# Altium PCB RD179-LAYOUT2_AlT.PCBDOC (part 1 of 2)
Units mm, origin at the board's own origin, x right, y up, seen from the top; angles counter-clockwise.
Board outline 130 x 85 mm, 2 copper layers (TOP, BOTTOM), stack 0 mm thick; 157 components, 104 nets, 823 pads, 0 vias.
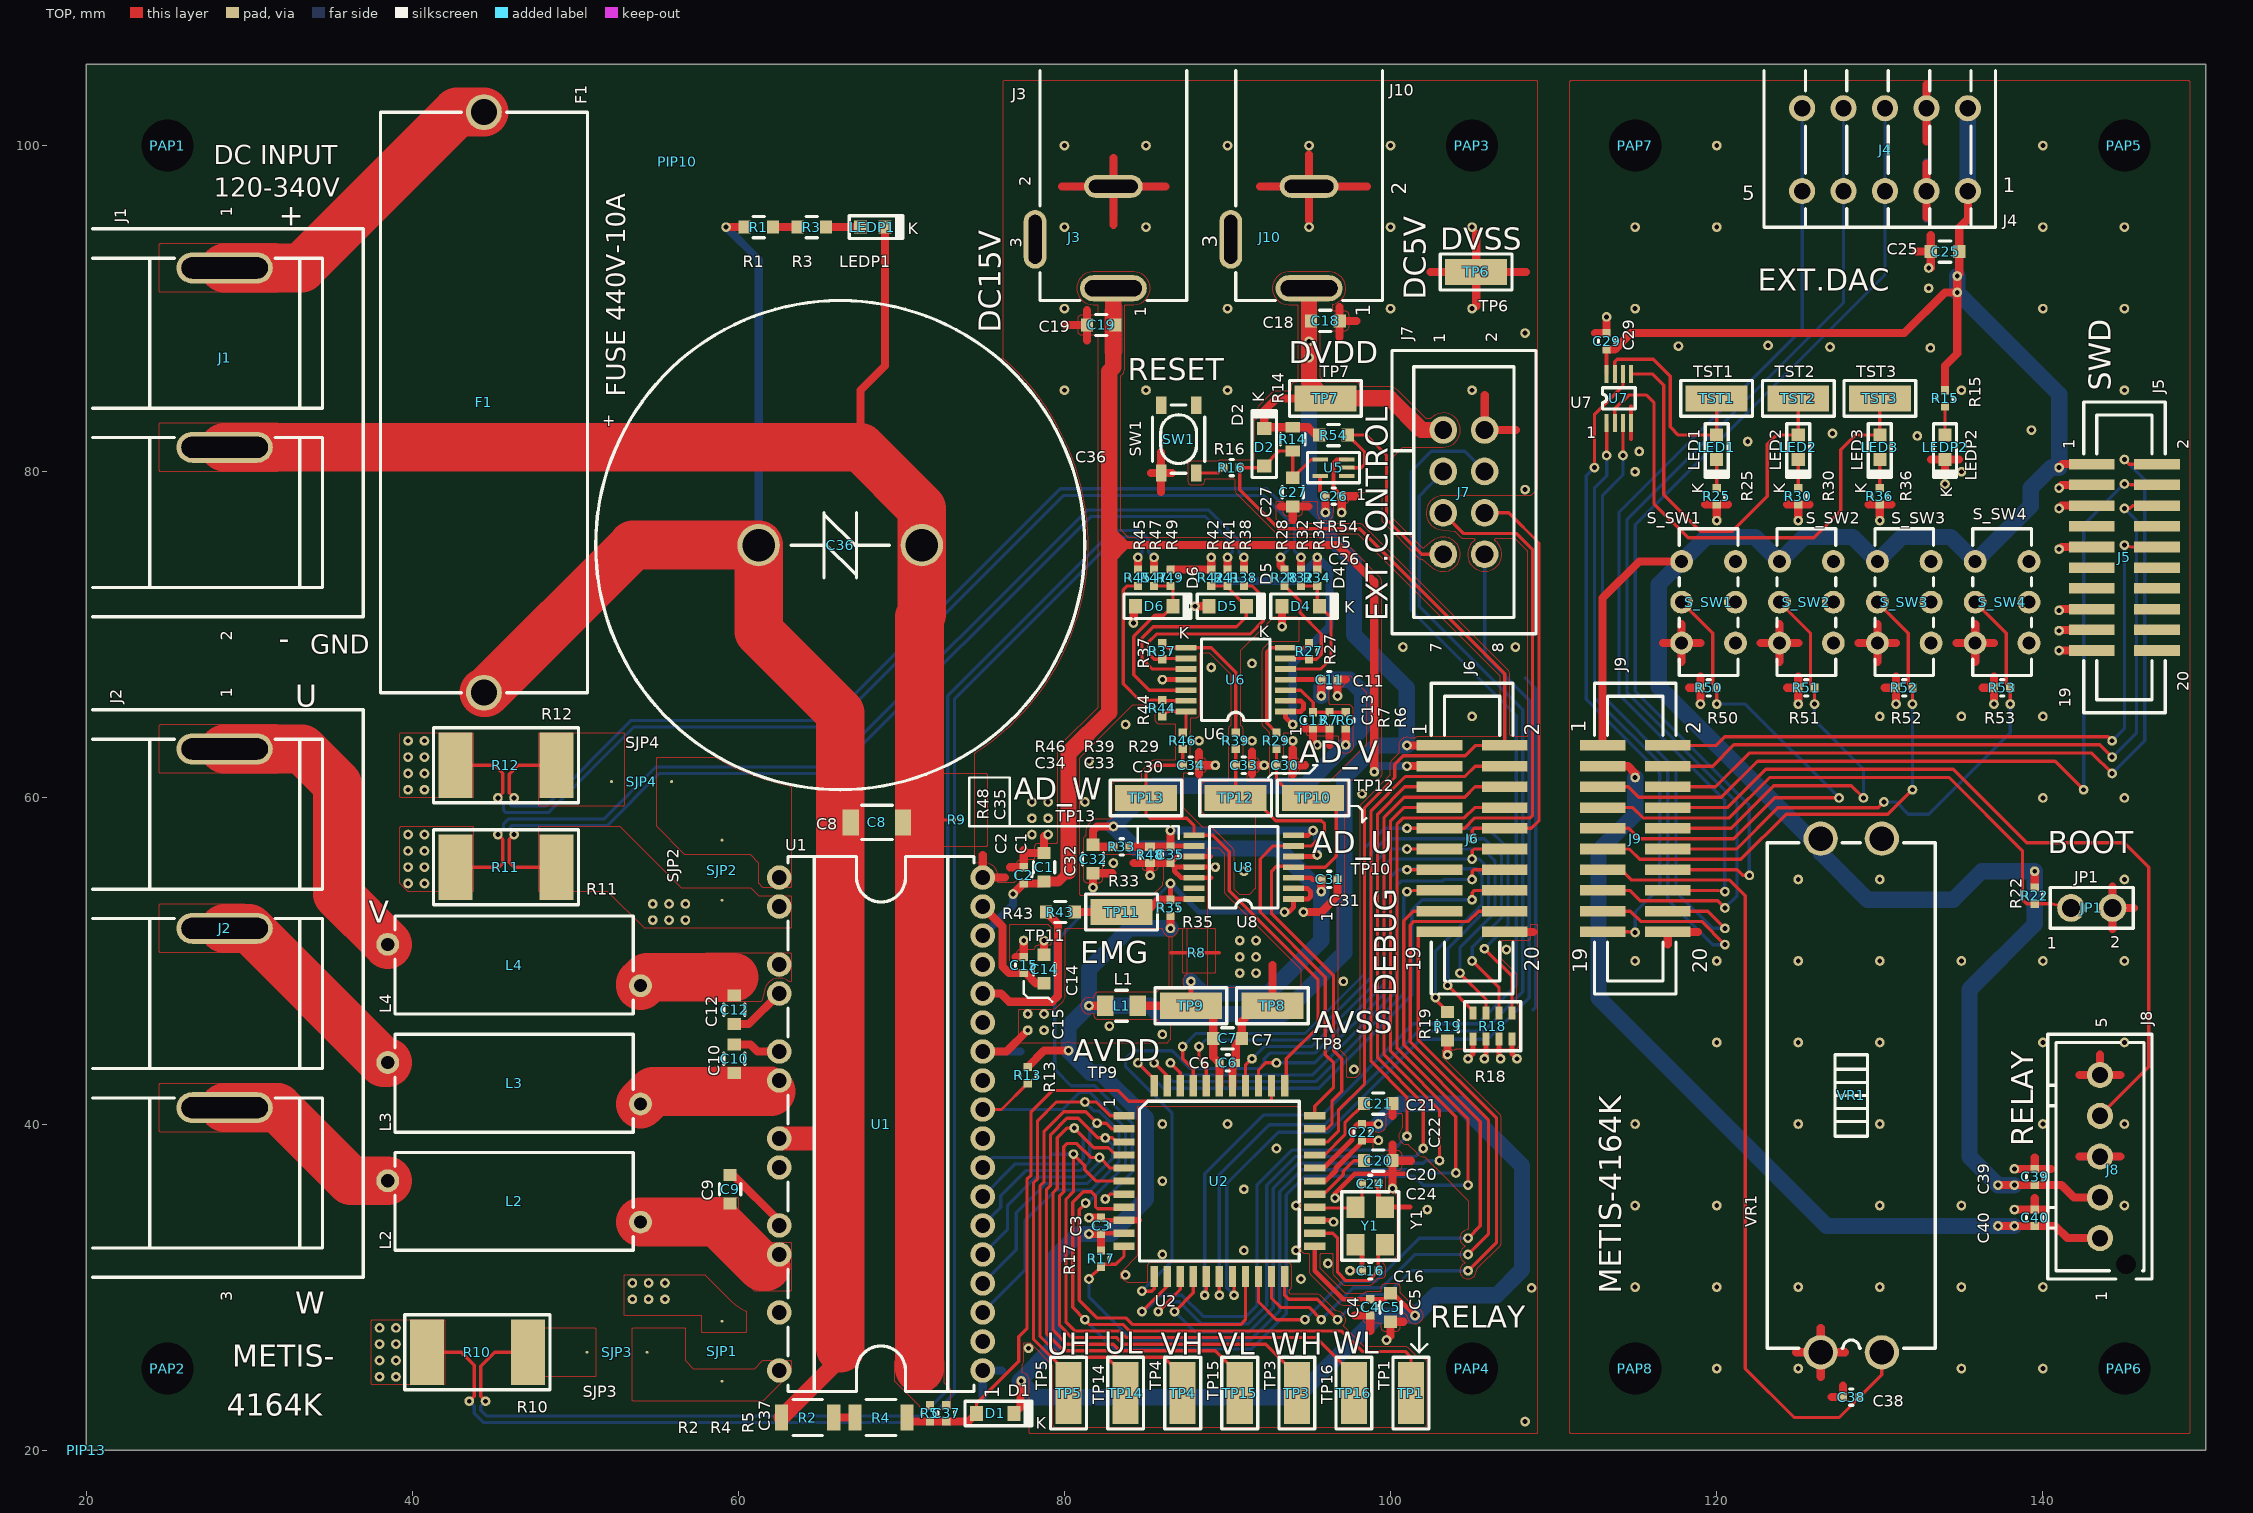
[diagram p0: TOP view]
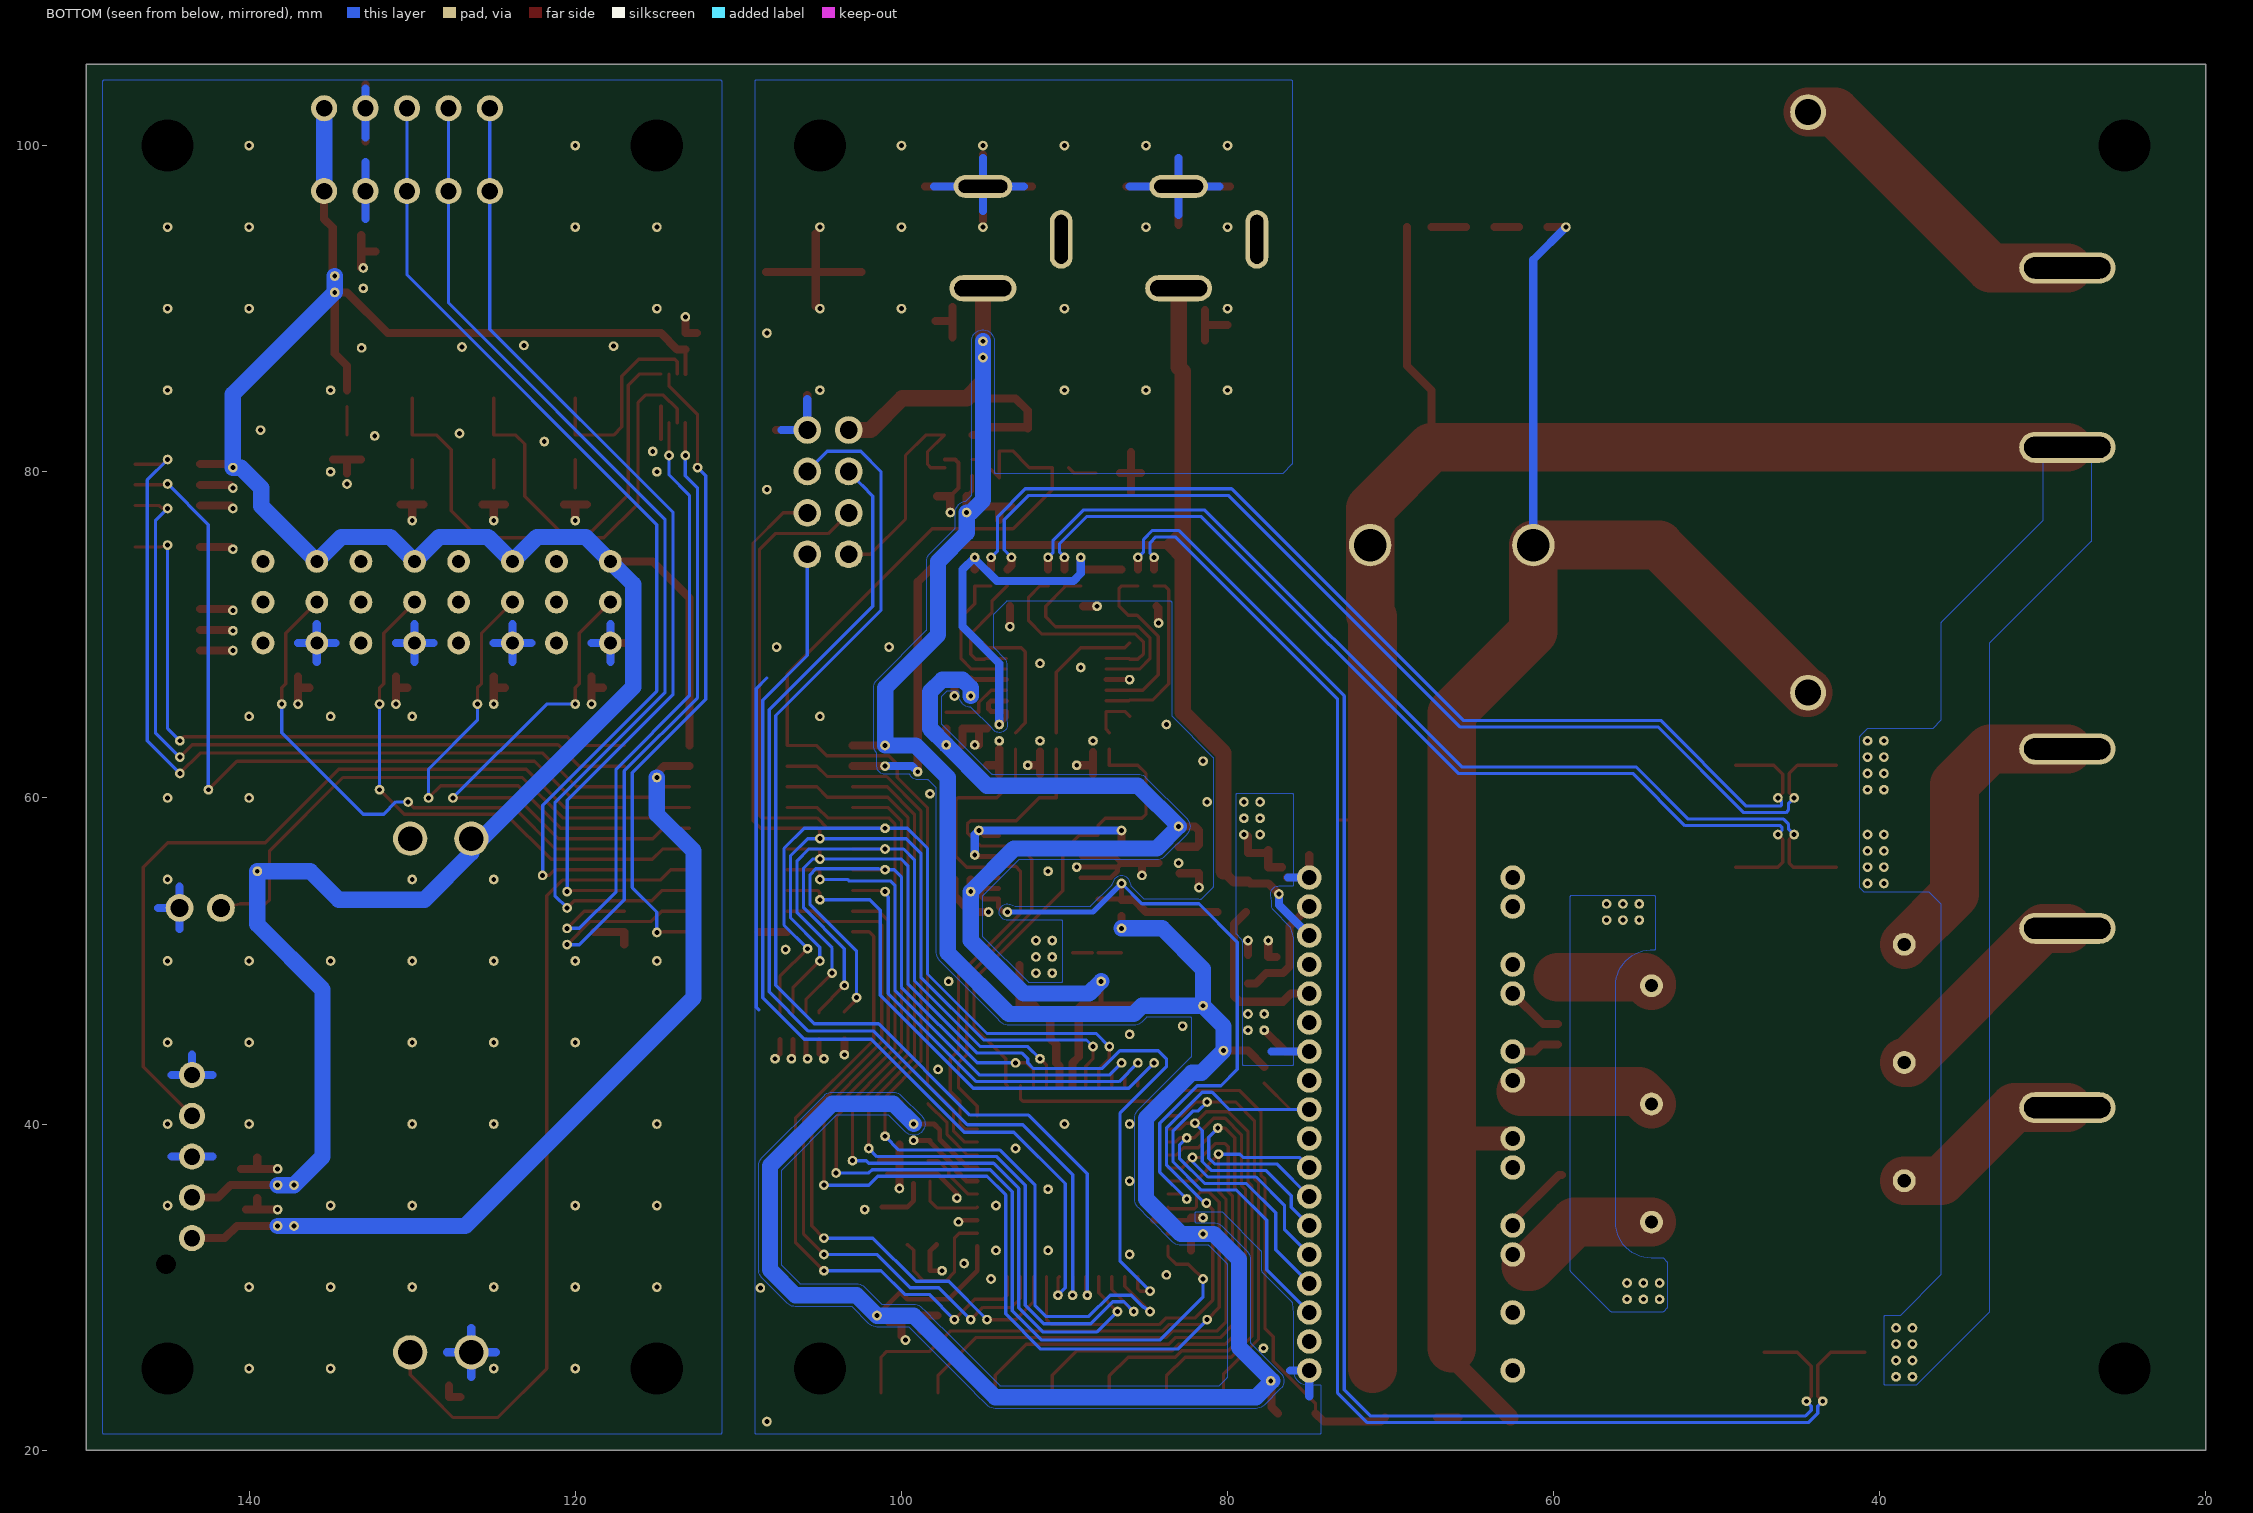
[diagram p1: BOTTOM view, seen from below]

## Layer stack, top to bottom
Top Solder: solder mask 0.0102, Solder Resist, Dk 3.5
TOP: signal copper (thickness not stored)
BOTTOM: signal copper (thickness not stored)
Bottom Solder: solder mask 0.0102, Solder Resist, Dk 3.5

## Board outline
20,20 20,105 150,105 150,20

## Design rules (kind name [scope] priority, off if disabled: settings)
AssemblyTestPointUsage [All] p0: scope1count=1 scope1_0_kind=Board scope1_0_value=Board scope2count=1 scope2_0_kind=Board scope2_0_value=Board commentlength=0
AssemblyTestpoint [All] p0: scope1count=1 scope1_0_kind=Board scope1_0_value=Board scope2count=1 scope2_0_kind=Board scope2_0_value=Board commentlength=0
Clearance [All] p0: scope1count=1 scope1_0_kind=Board scope1_0_value=Board scope2count=1 scope2_0_kind=Board scope2_0_value=Board commentlength=0 gap=0.2
Clearance [All] p1: gap=0.2 ignorepadtopadclearanceinfootprint=TRUE except(0.3: SMDPad-THPad THPad-THPad THPad-Via Via-Via; 0.5: SMDPad-SMDPad; 1: Arc-Hole Track-Hole SMDPad-Hole THPad-Hole Via-Hole Fill-Hole Poly-Hole Region-Hole Text-Hole)
ComponentClearance [All] p0: scope1count=1 scope1_0_kind=Board scope1_0_value=Board scope2count=1 scope2_0_kind=Board scope2_0_value=Board commentlength=0 gap=0.254 collisioncheckmode=3
DiffPairsRouting [All] p0: scope1count=1 scope1_0_kind=Board scope1_0_value=Board scope2count=1 scope2_0_kind=Board scope2_0_value=Board commentlength=0
FabricationTestPointUsage [All] p0: scope1count=1 scope1_0_kind=Board scope1_0_value=Board scope2count=1 scope2_0_kind=Board scope2_0_value=Board commentlength=0 valid=0 allowmultiple=FALSE
FabricationTestpoint [All] p0: scope1count=1 scope1_0_kind=Board scope1_0_value=Board scope2count=1 scope2_0_kind=Board scope2_0_value=Board commentlength=0 side=3 testpointundercomponent=TRUE minsize=1.016 maxsize=2.54 preferedsize=1.524 minholesize=0 maxholesize=1.016 preferedholesize=0.813 testpointgrid=0.025
FanoutControl Fanout_BGA [All] p0 off: scope1count=1 scope1_0_kind=Board scope1_0_value=Board scope2count=1 scope2_0_kind=Board scope2_0_value=Board commentlength=69 // Protel DXP Scope 1 Expression Was: IsBGA   Fanout_BGA (Default Rule)
FanoutControl Fanout_LCC [All] p0 off: scope1count=1 scope1_0_kind=Board scope1_0_value=Board scope2count=1 scope2_0_kind=Board scope2_0_value=Board commentlength=69 // Protel DXP Scope 1 Expression Was: IsLCC   Fanout_LCC (Default Rule)
FanoutControl Fanout_SOIC [All] p0 off: scope1count=1 scope1_0_kind=Board scope1_0_value=Board scope2count=1 scope2_0_kind=Board scope2_0_value=Board commentlength=71 // Protel DXP Scope 1 Expression Was: IsSOIC   Fanout_SOIC (Default Rule)
FanoutControl Fanout_Small [All] p0 off: scope1count=1 scope1_0_kind=Board scope1_0_value=Board scope2count=1 scope2_0_kind=Board scope2_0_value=Board commentlength=84 // Protel DXP Scope 1 Expression Was: (CompPinCount < 5)   Fanout_Small (Default Rule)
FanoutControl Fanout_Default [All] p0: scope1count=1 scope1_0_kind=Board scope1_0_value=Board scope2count=1 scope2_0_kind=Board scope2_0_value=Board commentlength=30 // Fanout_Default (Default Rule)
Height [All] p0: scope1count=1 scope1_0_kind=Board scope1_0_value=Board scope2count=1 scope2_0_kind=Board scope2_0_value=Board commentlength=0
HoleSize [All] p0: scope1count=1 scope1_0_kind=Board scope1_0_value=Board scope2count=1 scope2_0_kind=Board scope2_0_value=Board commentlength=0 absolutevalues=TRUE maxlimit=100 minlimit=0.001 maxpercent=80.000 minpercent=20.000
HoleSize [All] p1: absolutevalues=TRUE maxlimit=100 minlimit=0.001 maxpercent=80.000 minpercent=20.000
HoleToHoleClearance [All] p0: scope1count=1 scope1_0_kind=Board scope1_0_value=Board scope2count=1 scope2_0_kind=Board scope2_0_value=Board commentlength=0
HoleToHoleClearance [All] p1: gap=0.6 allowstackedmicrovias=FALSE
LayerPairs [All] p0: scope1count=1 scope1_0_kind=Board scope1_0_value=Board scope2count=1 scope2_0_kind=Board scope2_0_value=Board commentlength=0 enforce=TRUE
MinimumSolderMaskSliver [All] p0: scope1count=1 scope1_0_kind=Board scope1_0_value=Board scope2count=1 scope2_0_kind=Board scope2_0_value=Board commentlength=0
MinimumSolderMaskSliver [All] p1: minsoldermaskwidth=0.15
NetAntennae [All] p0: scope1count=1 scope1_0_kind=Board scope1_0_value=Board scope2count=1 scope2_0_kind=Board scope2_0_value=Board commentlength=0
NetAntennae [All] p1: netantennaetolerance=100
PasteMaskExpansion [All] p0: scope1count=1 scope1_0_kind=Board scope1_0_value=Board scope2count=1 scope2_0_kind=Board scope2_0_value=Board commentlength=0 expansion=0
PlaneClearance [All] p0: scope1count=1 scope1_0_kind=Board scope1_0_value=Board scope2count=1 scope2_0_kind=Board scope2_0_value=Board commentlength=0 clearance=0.001
PlaneClearance [All] p1: clearance=0.001
PlaneConnect [All] p0: scope1count=1 scope1_0_kind=Board scope1_0_value=Board scope2count=1 scope2_0_kind=Board scope2_0_value=Board commentlength=0 planeconnectstyle=Direct reliefexpansion=0.508 reliefentries=4 reliefconductorwidth=0.254 reliefairgap=0.254
PlaneConnect [All] p1: planeconnectstyle=Direct reliefexpansion=0.508 reliefentries=4 reliefconductorwidth=0.254 reliefairgap=0.254
PolygonConnect [All] p0: scope1count=1 scope1_0_kind=Board scope1_0_value=Board scope2count=1 scope2_0_kind=Board scope2_0_value=Board commentlength=0 connectstyle=Direct reliefconductorwidth=0.254 reliefentries=4 polygonreliefangle="90 Angle"
PolygonConnect [All] p1: connectstyle=Direct reliefconductorwidth=0.254 reliefentries=4 polygonreliefangle="90 Angle" airgapwidth=0.254
RoutingCorners [All] p0: scope1count=1 scope1_0_kind=Board scope1_0_value=Board scope2count=1 scope2_0_kind=Board scope2_0_value=Board commentlength=0 cornerstyle=45-Degree minsetback=2.54 maxsetback=2.54
RoutingLayers [All] p0: scope1count=1 scope1_0_kind=Board scope1_0_value=Board scope2count=1 scope2_0_kind=Board scope2_0_value=Board commentlength=0 top layer=Automatic bottom layer=Automatic
RoutingPriority [All] p0: scope1count=1 scope1_0_kind=Board scope1_0_value=Board scope2count=1 scope2_0_kind=Board scope2_0_value=Board commentlength=0
RoutingTopology [All] p0: scope1count=1 scope1_0_kind=Board scope1_0_value=Board scope2count=1 scope2_0_kind=Board scope2_0_value=Board commentlength=0 topology=Shortest
RoutingVias [All] p0: scope1count=1 scope1_0_kind=Board scope1_0_value=Board scope2count=1 scope2_0_kind=Board scope2_0_value=Board commentlength=0 holewidth=0.1 width=0.1 viastyle="Through Hole" minholewidth=0.001 minwidth=0.001 maxholewidth=100 maxwidth=100
RoutingVias [All] p1: holewidth=0.1 width=0.1 viastyle="Through Hole" minholewidth=0.001 minwidth=0.001 maxholewidth=100 maxwidth=100
ShortCircuit [All] p0: scope1count=1 scope1_0_kind=Board scope1_0_value=Board scope2count=1 scope2_0_kind=Board scope2_0_value=Board commentlength=0 allowed=FALSE
SilkToBoardRegionClearance [All] p0: scope1count=1 scope1_0_kind=Board scope1_0_value=Board scope2count=1 scope2_0_kind=Board scope2_0_value=Board commentlength=0
SilkToSilkClearance [All] p0: scope1count=1 scope1_0_kind=Board scope1_0_value=Board scope2count=1 scope2_0_kind=Board scope2_0_value=Board commentlength=0
SilkToSilkClearance [All] p1: silktosilkclearance=0.001
SilkToSolderMaskClearance [All] p0 off: scope1count=1 scope1_0_kind=Board scope1_0_value=Board scope2count=1 scope2_0_kind=Board scope2_0_value=Board commentlength=44 // Protel DXP Scope 1 Expression Was: IsPad
SilkToSolderMaskClearance [IsPad] p1: minsilkscreentomaskgap=0.15 clearancetoexposedcopper=TRUE
SolderMaskExpansion [All] p0: scope1count=1 scope1_0_kind=Board scope1_0_value=Board scope2count=1 scope2_0_kind=Board scope2_0_value=Board commentlength=0 expansion=0.001
SolderMaskExpansion [All] p1: expansion=0.001
UnRoutedNet [All] p0: scope1count=1 scope1_0_kind=Board scope1_0_value=Board scope2count=1 scope2_0_kind=Board scope2_0_value=Board commentlength=0
UnpouredPolygon [All] p0: scope1count=1 scope1_0_kind=Board scope1_0_value=Board scope2count=1 scope2_0_kind=Board scope2_0_value=Board commentlength=0
Width [All] p0: scope1count=1 scope1_0_kind=Board scope1_0_value=Board scope2count=1 scope2_0_kind=Board scope2_0_value=Board commentlength=0 maxlimit=1000 minlimit=2539.975 preferedwidth=0
Width [All] p1: maxlimit=1000 minlimit=2539.975 preferedwidth=0 toplayer_minwidth=0 bottomlayer_minwidth=0 minimp=50.000000 maximp=50.000000 favimp=50.000000
22 further rules are at their usual default settings.

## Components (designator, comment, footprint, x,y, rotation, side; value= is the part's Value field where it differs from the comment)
C1 "CRC1608DEF-R" CRC1608DEF-R 78.75,55.75 r90 top
C2 "CRC1005DEF-R" CRC1005DEF-R 77.5,55.25 r90 top
C3 "CRC1005DEF-R" CRC1005DEF-R 82.25,33.75 r90 top
C4 "CRC1005DEF-R" CRC1005DEF-R 98.75,28.75 r270 top
C5 "CRC1608DEF-R" CRC1608DEF-R 100,28.75 r270 top
C6 "CRC1005DEF-R" CRC1005DEF-R 90,43.75 r0 top
C7 "CRC1608DEF-R" CRC1608DEF-R 90,45.25 r0 top
C8 "CC3216DEF-R" CC3216DEF-R 68.5,58.5 r0 top
C9 "CRC1608DEF-R" CRC1608DEF-R 59.5,36 r270 top
C10 "CRC1608DEF-R" CRC1608DEF-R 59.75,44 r270 top
C11 "CRC1005DEF-R" CRC1005DEF-R 96.25,67.25 r180 top
C12 "CRC1608DEF-R" CRC1608DEF-R 59.75,47 r90 top
C13 "CRC1005DEF-R" CRC1005DEF-R 95.25,64.75 r90 top
C14 "CRC1608DEF-R" CRC1608DEF-R 78.75,49.5 r90 top
C15 "CRC1005DEF-R" CRC1005DEF-R 77.5,49.75 r90 top
C16 "CRC1005DEF-R" CRC1005DEF-R 98.75,31 r180 top
C18 "CRC1608DEF-R" CRC1608DEF-R 96,89.25 r0 top
C19 "CRC1608DEF-R" CRC1608DEF-R 82.25,89 r180 top
C20 "CRC1608DEF-R" CRC1608DEF-R 99.25,37.75 r0 top
C21 "CRC1608DEF-R" CRC1608DEF-R 99.25,41.25 r0 top
C22 "CRC1005DEF-R" CRC1005DEF-R 98.25,39.5 r270 top
C24 "CRC1005DEF-R" CRC1005DEF-R 98.75,36.35 r0 top
C25 "CRC1608DEF-R" CRC1608DEF-R 134,93.5 r180 top
C26 "CRC1005DEF-R" CRC1005DEF-R 96.5,78.5 r0 top
C27 "CRC1608DEF-R" CRC1608DEF-R 94,78.75 r270 top
C29 "CRC1005DEF-R" CRC1005DEF-R 113.25,88 r90 top
C30 "CRC1005DEF-R" CRC1005DEF-R 93.5,62 r0 top
C31 "CRC1005DEF-R" CRC1005DEF-R 96.25,55 r0 top
C32 "CRC1608DEF-R" CRC1608DEF-R 81.75,56.25 r270 top
C33 "CRC1005DEF-R" CRC1005DEF-R 91,62 r0 top
C34 "CRC1005DEF-R" CRC1005DEF-R 87.75,62 r0 top
C35 "CRC1005DEF-R" CRC1005DEF-R 86.5,56.5 r270 top
C36 "DDC300000" DDC300000 66.25,75.5 r0 top
C37 "CRC1005DEF-R" CRC1005DEF-R 72.75,22.25 r90 top
C38 "CRC1005DEF-R" CRC1005DEF-R 128.25,23.25 r180 top
C39 "CRC1005DEF-R" CRC1005DEF-R 139.5,36.75 r90 top
C40 "CRC1005DEF-R" CRC1005DEF-R 139.5,34.25 r90 top
D1 "CDUSC05-R" CDUSC05-R 75.75,22.25 r180 top
D2 "CDUSC05-R" CDUSC05-R 92.25,81.5 r270 top
D4 "CDUSC05-R" CDUSC05-R 94.5,71.75 r180 top
D5 "CDUSC05-R" CDUSC05-R 90,71.75 r180 top
D6 "CDUSC05-R" CDUSC05-R 85.5,71.75 r180 top
F1 "DFU351200" DFU351200 44.4,84.25 r270 top
J1 "OTB-650-2P_R00" OTB-650-2P_R00 28.5,83 r270 top
J2 "OTB-650-3P_R00" OTB-650-3P_R00 28.5,48 r270 top
J3 "2DC-0005D100_R00" 2DC-0005D100_R00 83,91.25 r90 top
J4 "ML-700-NV-5P_R00" ML-700-NV-5P_R00 130,100 r180 top
J5 "3220-20-0300-00_R00-R" 3220-20-0300-00_R00-R 145,74.75 r270 top
J6 "3220-20-0300-00_R00-R" 3220-20-0300-00_R00-R 105,57.5 r270 top
J7 "75869-332LF_R00" 75869-332LF_R00 104.5,78.75 r270 top
J8 "B05B-XASK-1-A_R00" B05B-XASK-1-A_R00 143.5,38 r270 top
J9 "3220-20-0300-00_R00-R" 3220-20-0300-00_R00-R 115,57.5 r270 top
J10 "2DC-0005D100_R00" 2DC-0005D100_R00 95,91.25 r90 top
JP1 "PH-1X02SG_R00" PH-1X02SG_R00 143,53.25 r0 top
L1 "CL2125DEF-R" CL2125DEF-R 83.5,47.25 r180 top
L2 "DL146001" DL146001 46.25,35.25 r0 top
L3 "DL146001" DL146001 46.25,42.5 r0 top
L4 "DL146001" DL146001 46.25,49.75 r0 top
LED1 "LTST-C190_R00-R" LTST-C190_R00-R 120,81.5 r90 top
LED2 "LTST-C190_R00-R" LTST-C190_R00-R 125,81.5 r90 top
LED3 "LTST-C190_R00-R" LTST-C190_R00-R 130,81.5 r90 top
LEDP1 "LTST-C190_R00-R" LTST-C190_R00-R 68.25,95 r180 top
LEDP2 "LTST-C190_R00-R" LTST-C190_R00-R 134,81.5 r90 top
PAP1 "NH3.2-00" NH3.2-00 25,100 r0 top
PAP2 "NH3.2-00" NH3.2-00 25,25 r0 top
PAP3 "NH3.2-00" NH3.2-00 105,100 r0 top
PAP4 "NH3.2-00" NH3.2-00 105,25 r0 top
PAP5 "NH3.2-00" NH3.2-00 145,100 r0 top
PAP6 "NH3.2-00" NH3.2-00 145,25 r0 top
PAP7 "NH3.2-00" NH3.2-00 115,100 r0 top
PAP8 "NH3.2-00" NH3.2-00 115,25 r0 top
PIP10 "LOGO-TOSHIBA_NEW" LOGO-TOSHIBA_NEW 56.25,99 r0 top
PIP11 "L2-00" L2-00 20,1.5 r0 top
PIP12 "ANAKOUSA-00" ANAKOUSA-00 163,-20 r0 top
PIP13 "ZAHYO_ORG-00" ZAHYO_ORG-00 20,20 r0 top
R1 "CRC1608DEF-R" CRC1608DEF-R 61.25,95 r0 top
R2 "CR3216DEF-R" CR3216DEF-R 64.25,22 r0 top
R3 "CRC1608DEF-R" CRC1608DEF-R 64.5,95 r0 top
R4 "CR3216DEF-R" CR3216DEF-R 68.75,22 r0 top
R5 "CRC1005DEF-R" CRC1005DEF-R 71.75,22.25 r90 top
R6 "CRC1005DEF-R" CRC1005DEF-R 97.25,64.75 r90 top
R7 "CRC1005DEF-R" CRC1005DEF-R 96.25,64.75 r270 top
R8 "CX000275-R" CX000275-R 88.1,50.5 r180 top
R9 "CX000275-R" CX000275-R 73.4,58.65 r180 top
R10 "CR643218-R" CR643218-R 44,26 r0 top
R11 "CR643218-R" CR643218-R 45.75,55.75 r0 top
R12 "CR643218-R" CR643218-R 45.75,62 r0 top
R13 "CRC1005DEF-R" CRC1005DEF-R 77.75,43 r90 top
R14 "CRC160858-R" CRC160858-R 94,82 r90 top
R15 "CRC1005DEF-R" CRC1005DEF-R 134,84.5 r90 top
R16 "CRC1005DEF-R" CRC1005DEF-R 90.25,80.25 r180 top
R17 "CRC1005DEF-R" CRC1005DEF-R 82.25,31.75 r270 top
R18 "CRA321633-R" CRA321633-R 106.25,46 r0 top
R19 "CRC1608DEF-R" CRC1608DEF-R 103.5,46 r270 top
R22 "CRC1005DEF-R" CRC1005DEF-R 139.5,54 r270 top
R25 "CRC1005DEF-R" CRC1005DEF-R 120,78.5 r270 top
R27 "CRC1005DEF-R" CRC1005DEF-R 95,69 r270 top
R28 "CRC1005DEF-R" CRC1005DEF-R 93.5,73.5 r90 top
R29 "CRC1005DEF-R" CRC1005DEF-R 93,63.5 r90 top
R30 "CRC1005DEF-R" CRC1005DEF-R 125,78.5 r270 top
R32 "CRC1005DEF-R" CRC1005DEF-R 94.5,73.5 r90 top
R33 "CRC1005DEF-R" CRC1005DEF-R 83.5,57 r0 top
R34 "CRC1005DEF-R" CRC1005DEF-R 95.5,73.5 r90 top
R35 "CRC1005DEF-R" CRC1005DEF-R 86.5,53.25 r90 top
R36 "CRC1005DEF-R" CRC1005DEF-R 130,78.5 r270 top
R37 "CRC1005DEF-R" CRC1005DEF-R 86,69 r270 top
R38 "CRC1005DEF-R" CRC1005DEF-R 91,73.5 r90 top
R39 "CRC1005DEF-R" CRC1005DEF-R 90.5,63.5 r90 top
R41 "CRC1005DEF-R" CRC1005DEF-R 90,73.5 r90 top
R42 "CRC1005DEF-R" CRC1005DEF-R 89,73.5 r90 top
R43 "CRC1608DEF-R" CRC1608DEF-R 79.75,53 r0 top
R44 "CRC1005DEF-R" CRC1005DEF-R 86,65.5 r90 top
R45 "CRC1005DEF-R" CRC1005DEF-R 84.5,73.5 r90 top
R46 "CRC1005DEF-R" CRC1005DEF-R 87.25,63.5 r90 top
R47 "CRC1005DEF-R" CRC1005DEF-R 85.5,73.5 r90 top
R48 "CRC100512-R" CRC100512-R 85.25,56.5 r270 top
R49 "CRC1005DEF-R" CRC1005DEF-R 86.5,73.5 r90 top
R50 "CRC1005DEF-R" CRC1005DEF-R 119.5,66.75 r180 top
R51 "CRC1005DEF-R" CRC1005DEF-R 125.5,66.75 r180 top
R52 "CRC1005DEF-R" CRC1005DEF-R 131.5,66.75 r180 top
R53 "CRC1005DEF-R" CRC1005DEF-R 137.5,66.75 r180 top
R54 "CRC1608DEF-R" CRC1608DEF-R 96.5,82.25 r0 top
S_SW1 "IS-1250_R00" IS-1250_R00 119.5,72 r270 top
S_SW2 "IS-1250_R00" IS-1250_R00 125.5,72 r270 top
S_SW3 "IS-1250_R00" IS-1250_R00 131.5,72 r270 top
S_SW4 "IS-1250_R00" IS-1250_R00 137.5,72 r270 top
SJP1 "CJP0002116-R" CJP0002116-R 59,26 r90 top
SJP2 "CJP0002116-R" CJP0002116-R 59,55.5 r90 top
SJP3 "CJP0002116-R" CJP0002116-R 52.5,26 r0 top
SJP4 "CJP0002116-R" CJP0002116-R 54,61 r0 top
SW1 "SKRPABE010_R01-R" SKRPABE010_R01-R 87,82 r90 top
TP1 "CTP321600-R" CTP321600-R 101.25,23.5 r270 top
TP3 "CTP321600-R" CTP321600-R 94.25,23.5 r270 top
TP4 "CTP321600-R" CTP321600-R 87.25,23.5 r270 top
TP5 "CTP321600-R" CTP321600-R 80.25,23.5 r90 top
TP6 "CTP321600-R" CTP321600-R 105.25,92.25 r180 top
TP7 "CTP321600-R" CTP321600-R 96,84.5 r0 top
TP8 "CTP321600-R" CTP321600-R 92.75,47.25 r180 top
TP9 "CTP321600-R" CTP321600-R 87.75,47.25 r180 top
TP10 "CTP321600-R" CTP321600-R 95.25,60 r180 top
TP11 "CTP321600-R" CTP321600-R 83.5,53 r180 top
TP12 "CTP321600-R" CTP321600-R 90.5,60 r0 top
TP13 "CTP321600-R" CTP321600-R 85,60 r0 top
TP14 "CTP321600-R" CTP321600-R 83.75,23.5 r90 top
TP15 "CTP321600-R" CTP321600-R 90.75,23.5 r90 top
TP16 "CTP321600-R" CTP321600-R 97.75,23.5 r90 top
TST1 "CTP321600-R" CTP321600-R 120,84.5 r0 top
TST2 "CTP321600-R" CTP321600-R 125,84.5 r0 top
TST3 "CTP321600-R" CTP321600-R 130,84.5 r0 top
U1 "DP030-1.778-01" DP030-1.778-01 68.75,40 r90 top
U2 "QP044-0.8-02-R" QP044-0.8-02-R 89.5,36.5 r270 top
U5 "CIC005-0.5-00-R" CIC005-0.5-00-R 96.5,80.25 r90 top
U6 "SP014-0.65-06-R" SP014-0.65-06-R 90.5,67.25 r90 top
U7 "SP008-0.5-00-R" SP008-0.5-00-R 114,84.5 r0 top
U8 "SP014-0.65-06-R" SP014-0.65-06-R 91,55.75 r90 top
VR1 "RS15M111J002_R00" RS15M111J002_R00 128.25,41.75 r90 top
Y1 "CXL322568-R" CXL322568-R 98.75,33.75 r90 top

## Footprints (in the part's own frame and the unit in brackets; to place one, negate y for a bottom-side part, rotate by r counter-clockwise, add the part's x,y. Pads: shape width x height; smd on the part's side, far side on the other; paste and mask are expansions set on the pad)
2DC-0005D100_R00 [mm] "KC00080BKP"
  oval 1.6x4.1 / inner round 0 / far side oval 1.6x4.1 hole 1 slot 3.5 at 90 deg paste-4.2 mask+0: 1(0,0)
  oval 1.4x3.6 / inner round 0 / far side oval 1.4x3.6 hole 0.8 slot 3 at 90 deg paste-3.7 mask+0: 2(6.25,0)
  oval 3.6x1.4 / inner round 0 / far side oval 3.6x1.4 hole 0.8 slot 3 at 0 deg paste-3.7 mask+0: 3(3,4.8)
  silkscreen extent -0.75,-4.5 13.35,4.5
3220-20-0300-00_R00-R [mm] "KC00080BKP"
  rect 0.65x2.8 smd paste-2.9 mask+0: 1(-5.715,-2) 2(-5.715,2) 3(-4.445,-2) 4(-4.445,2) 5(-3.175,-2) 6(-3.175,2) 7(-1.905,-2) 8(-1.905,2) 9(-0.635,-2) 10(-0.635,2) 11(0.635,-2) 12(0.635,2) 13(1.905,-2) 14(1.905,2) 15(3.175,-2) 16(3.175,2) 17(4.445,-2) 18(4.445,2) 19(5.715,-2) 20(5.715,2)
  silkscreen extent -9.53,-2.5 9.53,2.5
75869-332LF_R00 [mm] "KC00080BKP"
  round 1.7 / inner round 0 / far side round 1.7 hole 1.1 paste-1.8 mask+0: 1(-3.81,-1.27) 2(-3.81,1.27) 3(-1.27,-1.27) 4(-1.27,1.27) 5(1.27,-1.27) 6(1.27,1.27) 7(3.81,-1.27) 8(3.81,1.27)
  silkscreen extent -8.68,-4.41 8.68,4.41
ANAKOUSA-00 [mm] "KC00080BKP"
B05B-XASK-1-A_R00 [mm] "KC00080BKP"
  round 1.6 / inner round 0 / far side round 1.6 hole 1 paste-1.7 mask+0: 1(5,0) 2(2.5,0) 3(0,0) 4(-2.5,0) 5(-5,0)
  round 0 hole 1.2 unplated paste-1.7 mask+0: ""(6.6,1.6)
  silkscreen extent -7.5,-3.2 7.5,3.2
CC3216DEF-R [mm] "KC00080BKP"
  rect 1x1.6 smd paste-1.7 mask+0: 1(-1.6,0) 2(1.6,0)
  silkscreen extent -0.95,-1.05 0.95,1.05
CDUSC05-R [mm] "KC00080BKP"
  rect 0.8x0.9 smd paste-1 mask+0: 1(1.15,0) 3(-1.15,0)
  silkscreen extent -2.25,-0.75 1.85,0.75
CIC005-0.5-00-R [mm] "KC00080BKP"
  rect 0.25x0.95 smd paste-1.05 mask+0: 1(-0.5,-0.825) 2(0,-0.825) 3(0.5,-0.825) 4(0.5,0.825) 5(-0.5,0.825)
  silkscreen extent -0.92,-1.6 0.92,1.6
CJP0002116-R [mil] "KC00080BKP"
  round 7 smd paste-7 mask+0: 1(-70,0) 2(75,0)
CL2125DEF-R [mm] "KC00080BKP"
  rect 1x1.25 smd paste-1.35 mask+0: 1(-1,0) 2(1,0)
  silkscreen extent -0.35,-0.95 0.35,0.95
CR3216DEF-R [mm] "KC00080BKP"
  rect 0.8x1.6 smd paste-1.7 mask+0: 1(-1.6,0) 2(1.6,0)
  silkscreen extent -0.9,-1.1 0.9,1.1
CR643218-R [mm] "KC00080BKP"
  rect 2.1x4 smd paste-4.1 mask+0: 1(-3.1,0) 2(3.1,0)
  silkscreen extent -4.45,-2.3 4.45,2.3
CRA321633-R [mm] "KC00080BKP"
  rect 0.45x0.8 smd paste-0.9 mask+0: 1(-1.2,-0.8) 2(-0.4,-0.8) 3(0.4,-0.8) 4(1.2,-0.8) 5(1.2,0.8) 6(0.4,0.8) 7(-0.4,0.8) 8(-1.2,0.8)
  silkscreen extent -1.73,-1.5 1.73,1.5
CRC1005DEF-R [mm] "KC00080BKP"
  rect 0.5x0.5 smd paste-0.6 mask+0: 1(-0.5,0) 2(0.5,0)
  silkscreen extent -0.1,-0.5 0.1,0.5
CRC1608DEF-R [mm] "KC00080BKP"
  rect 0.75x0.8 smd paste-0.9 mask+0: 1(-0.875,0) 2(0.875,0)
  silkscreen extent -0.35,-0.65 0.35,0.65
CRC100512-R [mm] "KC00080BKP"
  rect 0.5x0.6 smd paste-0.7 mask+0: 1(-0.5,0) 2(0.5,0)
  silkscreen extent -0.2,-0.6 0.2,0.6
CRC160858-R [mm] "KC00080BKP"
  rect 0.65x0.9 smd paste-1 mask+0: 1(-0.725,0) 2(0.725,0)
  silkscreen extent -0.35,-0.75 0.35,0.75
CTP321600-R [mm] "KC00080BKP"
  rect 3.8x1.6 smd paste-3.9 mask+0: 1(0,0)
  silkscreen extent -2.2,-1.1 2.2,1.1
CX000275-R [mm] "KC00080BKP"
  round 0.25 smd paste-0.25 mask+0: 1(-0.175,0) 2(0.175,0)
CXL322568-R [mm] "KC00080BKP"
  rect 1.3x1.1 smd paste-1.4 mask+0: 1(-1.15,-0.9) 2(1.15,-0.9) 3(1.15,0.9) 4(-1.15,0.9)
  silkscreen extent -2.1,-1.75 2.1,1.75
DDC300000 [mm] "KC00080BKP"
  round 2.6 / inner round 0 / far side round 2.6 hole 2 paste-2.7 mask+0: 1(-5,0) 2(5,0)
  silkscreen extent -15,-15 15,15
DFU351200 [mm] "KC00080BKP"
  round 2.2 / inner round 0 / far side round 2.2 hole 1.6 paste-2.3 mask+0: 1(-17.8,0) 2(17.8,0)
  silkscreen extent -17.8,-6.35 17.8,6.35
DL146001 [mm] "KC00080BKP"
  round 1.4 / inner round 0 / far side round 1.4 hole 0.8 paste-1.5 mask+0: 1(-7.75,1.27) 2(7.75,-1.27)
  silkscreen extent -7.3,-3 7.31,3
DP030-1.778-01 [mm] "KC00080BKP"
  round 1.5 / inner round 0 / far side round 1.5 hole 0.9 paste-1.6 mask+0: 1(-15.113,-6.235) 2(-13.335,-6.235) 3(-11.557,-6.235) 4(-9.779,-6.235) 5(-8.001,-6.235) 6(-6.223,-6.235) 7(-4.445,-6.235) 8(-2.667,-6.235) 9(-0.889,-6.235) 10(0.889,-6.235) 11(2.667,-6.235) 12(4.445,-6.235) 13(6.223,-6.235) 14(8.001,-6.235) 15(9.779,-6.235) 16(11.557,-6.235) 17(13.335,-6.235) 18(15.113,-6.235) 19(15.113,6.235) 20(13.335,6.235) 21(9.779,6.235) 22(8.001,6.235) 23(4.445,6.235) 24(2.667,6.235) 25(-0.889,6.235) 26(-2.667,6.235) 27(-6.223,6.235) 28(-8.001,6.235) 29(-11.557,6.235) 30(-15.113,6.235)
  silkscreen extent -16.4,-5.7 16.4,5.7
IS-1250_R00 [mm] "KC00080BKP"
  round 1.4 / inner round 0 / far side round 1.4 hole 0.8 paste-1.5 mask+0: 1(-2.5,-1.65) 2(0,-1.65) 3(2.5,-1.65) 4(2.5,1.65) 5(0,1.65) 6(-2.5,1.65)
  silkscreen extent -4.5,-1.8 4.5,1.8
L2-00 [mm] "KC00080BKP"
LOGO-TOSHIBA_NEW [mm] "KC00080BKP"
LTST-C190_R00-R [mm] "KC00080BKP"
  rect 0.8x0.8 smd paste-0.9 mask+0: 1(0.75,0) 2(-0.75,0)
  silkscreen extent -1.85,-0.7 1.45,0.7
ML-700-NV-5P_R00 [mm] "KC00080BKP"
  round 1.6 / inner round 0 / far side round 1.6 hole 1 paste-1.7 mask+0: 1(-5.4,-2.29) 1-2(-5.4,2.79) 2(-2.86,-2.29) 2-2(-2.86,2.79) 3(-0.32,-2.29) 3-2(-0.32,2.79) 4(2.22,-2.29) 4-2(2.22,2.79) 5(4.76,-2.29) 5-2(4.76,2.79)
  silkscreen extent -7.1,-4.6 7.1,5
NH3.2-00 [mm] "KC00080BKP"
  round 0 hole 3.2 unplated paste-3.7 mask+0: ""(0,0)
OTB-650-2P_R00 [mm] "KC00080BKP"
  oval 1.9x5.9 / inner round 0 / far side oval 1.9x5.9 hole 1.3 slot 5.3 at 90 deg paste-6 mask+0: 1(-9.5,0) 2(1.5,0)
  silkscreen extent -11.9,-8.1 11.9,8.5
OTB-650-3P_R00 [mm] "KC00080BKP"
  oval 1.9x5.9 / inner round 0 / far side oval 1.9x5.9 hole 1.3 slot 5.3 at 90 deg paste-6 mask+0: 1(-15,0) 2(-4,0) 3(7,0)
  silkscreen extent -17.4,-8.1 17.4,8.5
PH-1X02SG_R00 [mm] "KC00080BKP"
  round 1.7 / inner round 0 / far side round 1.7 hole 1.1 paste-1.8 mask+0: 1(-1.27,0) 2(1.27,0)
  silkscreen extent -2.54,-1.25 2.54,1.25
QP044-0.8-02-R [mm] "KC00080BKP"
  rect 0.45x1.3 smd paste-1.4 mask+0: 1(-4,-5.85) 2(-3.2,-5.85) 3(-2.4,-5.85) 4(-1.6,-5.85) 5(-0.8,-5.85) 6(0,-5.85) 7(0.8,-5.85) 8(1.6,-5.85) 9(2.4,-5.85) 10(3.2,-5.85) 11(4,-5.85) 23(4,5.85) 24(3.2,5.85) 25(2.4,5.85) 26(1.6,5.85) 27(0.8,5.85) 28(0,5.85) 29(-0.8,5.85) 30(-1.6,5.85) 31(-2.4,5.85) 32(-3.2,5.85) 33(-4,5.85)
  rect 1.3x0.45 smd paste-1.4 mask+0: 12(5.85,-4) 13(5.85,-3.2) 14(5.85,-2.4) 15(5.85,-1.6) 16(5.85,-0.8) 17(5.85,0) 18(5.85,0.8) 19(5.85,1.6) 20(5.85,2.4) 21(5.85,3.2) 22(5.85,4) 34(-5.85,4) 35(-5.85,3.2) 36(-5.85,2.4) 37(-5.85,1.6) 38(-5.85,0.8) 39(-5.85,0) 40(-5.85,-0.8) 41(-5.85,-1.6) 42(-5.85,-2.4) 43(-5.85,-3.2) 44(-5.85,-4)
  silkscreen extent -4.9,-4.9 4.9,4.9
RS15M111J002_R00 [mm] "KC00080BKP"
  round 2.1 / inner round 0 / far side round 2.1 hole 1.5 paste-2.2 mask+0: 1(-15.75,1.875) 2(-15.75,-1.875) 3(15.75,1.875) 4(15.75,-1.875)
  silkscreen extent -15.5,-5.15 15.5,5.15
SKRPABE010_R01-R [mm] "KC00080BKP"
  rect 1.05x0.65 smd paste-1.15 mask+0: 1(2.075,-1.075) 2(-2.075,-1.075) 3(2.075,1.075) 4(-2.075,1.075)
  silkscreen extent -2.1,-1.6 2.1,1.6
SP008-0.5-00-R [mm] "KC00080BKP"
  rect 0.25x1.1 smd paste-1.2 mask+0: 1(-0.75,-1.5) 2(-0.25,-1.5) 3(0.25,-1.5) 4(0.75,-1.5) 5(0.75,1.5) 6(0.25,1.5) 7(-0.25,1.5) 8(-0.75,1.5)
  silkscreen extent -1,-0.65 1,0.65
SP014-0.65-06-R [mm] "KC00080BKP"
  rect 0.35x1.3 smd paste-1.4 mask+0: 1(-1.95,-3.05) 2(-1.3,-3.05) 3(-0.65,-3.05) 4(0,-3.05) 5(0.65,-3.05) 6(1.3,-3.05) 7(1.95,-3.05) 8(1.95,3.05) 9(1.3,3.05) 10(0.65,3.05) 11(0,3.05) 12(-0.65,3.05) 13(-1.3,3.05) 14(-1.95,3.05)
  silkscreen extent -2.5,-2.1 2.5,2.1
ZAHYO_ORG-00 [mm] "KC00080BKP"

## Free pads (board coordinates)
  round 0.6 / inner round 0 / far side round 0.6 hole 0.3 paste-0.6 mask+0: ""(38,24.5) ""(38,25.5) ""(38,26.5) ""(38,27.5) ""(39,24.5) ""(39,25.5) ""(39,26.5) ""(39,27.5) ""(39.75,54.75) ""(39.75,55.75) ""(39.75,56.75) ""(39.75,57.75) ""(39.75,60.5) ""(39.75,61.5) ""(39.75,62.5) ""(39.75,63.5) ""(40.75,54.75) ""(40.75,55.75) ""(40.75,56.75) ""(40.75,57.75) ""(40.75,60.5) ""(40.75,61.5) ""(40.75,62.5) ""(40.75,63.5) ""(43.5,23) ""(44.5,23) ""(45.25,57.75) ""(45.25,60) ""(46.25,57.75) ""(46.25,60) ""(53.5,29.25) ""(53.5,30.25) ""(54.5,29.25) ""(54.5,30.25) ""(54.75,52.5) ""(54.75,53.5) ""(55.5,29.25) ""(55.5,30.25) ""(55.75,52.5) ""(55.75,53.5) ""(56.75,52.5) ""(56.75,53.5) ""(59.25,95) ""(76.85,54.1) ""(77.35,24.25) ""(77.5,51.25) ""(77.75,45.75) ""(77.75,46.75) ""(77.8,26.25) ""(78,57.75) ""(78,58.75) ""(78,59.75) ""(78.75,45.75) ""(78.75,46.75) ""(78.75,51.25) ""(79,57.75) ""(79,58.75) ""(79,59.75) ""(80,85) ""(80,90) ""(80,95) ""(80,100) ""(80.25,44.5) ""(80.55,38.15) ""(80.6,39.75) ""(81.25,28) ""(81.25,41.35) ""(81.25,59.75) ""(81.3,35.15) ""(81.5,30.5) ""(81.5,33.25) ""(81.5,34.25) ""(81.5,47.25) ""(81.5,62.25) ""(81.75,54.5) ""(82,40.05) ""(82.15,37.95) ""(82.5,35.4) ""(82.5,39.15) ""(82.75,46) ""(83,56) ""(83,58.25) ""(83.75,30.75) ""(83.75,64.5) ""(84.225,70.725) ""(84.5,43.75) ""(84.5,74.75) ""(84.75,28.5) ""(84.75,29.75) ""(85,85) ""(85,95) ""(85,100) ""(85.25,55.25) ""(85.5,43.75) ""(85.5,74.75) ""(85.75,28.5) ""(86,32) ""(86,36.5) ""(86,40) ""(86,45.5) ""(86,67.25) ""(86.5,43.75) ""(86.5,52) ""(86.5,54.75) ""(86.5,58) ""(86.75,28.5) ""(87.25,44.75) ""(87.75,48.75) ""(88,71.75) ""(88.25,44.75) ""(88.25,63.5) ""(88.6,29.5) ""(89,68) ""(89,74.75) ""(89.25,55.75) ""(89.25,62) ""(89.5,29.5) ""(90,40) ""(90,74.75) ""(90,85) ""(90,90) ""(90,100) ""(90.4,29.5) ""(90.75,49.25) ""(90.75,50.25) ""(90.75,51.25) ""(91,32.25) ""(91,36) ""(91,55.5) ""(91,74.75) ""(91.5,44) ""(91.5,63.5) ""(91.5,68.25) ""(91.75,49.25) ""(91.75,50.25) ""(91.75,51.25) ""(92.25,62) ""(93,38.5) ""(93,43.75) ""(93.25,74.75) ""(93.35,70.5) ""(93.5,53) ""(94,63.5) ""(94,64.5) ""(94.2,32.25) ""(94.2,35) ""(94.5,30.5) ""(94.5,74.75) ""(94.65,53) ""(94.75,28) ""(95,87) ""(95,88) ""(95,95) ""(95,100) ""(95.25,58) ""(95.5,56.5) ""(95.5,63.25) ""(95.5,74.75) ""(95.75,28) ""(95.75,54.25) ""(95.75,66.25) ""(96,77.5) ""(96.15,31.45) ""(96.5,34) ""(96.6,35.45) ""(96.75,28) ""(96.75,66.25) ""(97,77.5) ""(97.1,48.75) ""(97.25,63.25) ""(97.5,31) ""(97.75,43.35) ""(98.25,60.25) ""(99,61.6) ""(99.25,39) ""(99.25,40) ""(99.75,26.75) ""(100,90) ""(100,95) ""(100,100) ""(100.125,36.05) ""(100.75,69.25) ""(101,39.25) ""(101,54.25) ""(101,55.595) ""(101,56.865) ""(101,58.135) ""(101,61.945) ""(101,63.215) ""(101.5,28.25) ""(102,38.5) ""(102.25,34.75) ""(102.75,47.75) ""(103,37.75) ""(103.5,44.25) ""(103.5,48.5) ""(104,37) ""(104.25,49.25) ""(104.75,31) ""(104.75,32) ""(104.75,33) ""(104.75,36.25) ""(104.75,44) ""(105,50) ""(105,53.75) ""(105,55) ""(105,56.25) ""(105,57.5) ""(105,65) ""(105,85) ""(105,90) ""(105,95) ""(105.75,44) ""(105.75,50.75) ""(106.75,44) ""(107.1,50.7) ""(107.65,69.25) ""(107.75,44) ""(108.25,21.75) ""(108.25,78.9) ""(108.25,88.5) ""(108.65,29.95) ""(112.5,80.25) ""(113.25,81) ""(113.25,89.5) ""(114.25,81) ""(115,30) ""(115,35) ""(115,40) ""(115,50) ""(115,51.75) ""(115,61.25) ""(115,80) ""(115,90) ""(115,95) ""(115.25,81.25) ""(117.65,87.7) ""(119,65.75) ""(120,25) ""(120,30) ""(120,35) ""(120,45) ""(120,50) ""(120,65.75) ""(120,77) ""(120,95) ""(120,100) ""(120.5,51) ""(120.5,52) ""(120.5,53.25) ""(120.5,54.25) ""(121.9,81.85) ""(122,55.25) ""(123.15,87.75) ""(125,25) ""(125,30) ""(125,40) ""(125,45) ""(125,50) ""(125,55) ""(125,65.75) ""(125,77) ""(126,65.75) ""(126.95,87.65) ""(127.1,82.35) ""(127.5,60) ""(129,60) ""(130,30) ""(130,35) ""(130,40) ""(130,45) ""(130,50) ""(130,55) ""(130,65) ""(130,77) ""(130.25,59.75) ""(131,65.75) ""(132,60.5) ""(132,65.75) ""(132.3,82.2) ""(133,91.25) ""(133,92.5) ""(133.1,87.6) ""(134,79.25) ""(134.75,91) ""(134.75,92) ""(135,25) ""(135,30) ""(135,35) ""(135,50) ""(135,65) ""(135,80) ""(135,85) ""(137,65.75) ""(137.25,33.75) ""(137.25,36.25) ""(138,65.75) ""(138.25,33.75) ""(138.25,34.75) ""(138.25,36.25) ""(138.25,37.25) ""(139.3,82.55) ""(139.5,55.5) ""(140,25) ""(140,30) ""(140,40) ""(140,45) ""(140,50) ""(140,60) ""(140,65) ""(140,90) ""(140,95) ""(140,100) ""(141,69.035) ""(141,70.25) ""(141,71.5) ""(141,75.25) ""(141,77.75) ""(141,79) ""(141,80.25) ""(142.5,60.5) ""(144.25,61.5) ""(144.25,62.5) ""(144.25,63.5) ""(145,35) ""(145,40) ""(145,45) ""(145,50) ""(145,55) ""(145,60) ""(145,75.5) ""(145,77.75) ""(145,79.25) ""(145,80.75) ""(145,85) ""(145,90) ""(145,95)

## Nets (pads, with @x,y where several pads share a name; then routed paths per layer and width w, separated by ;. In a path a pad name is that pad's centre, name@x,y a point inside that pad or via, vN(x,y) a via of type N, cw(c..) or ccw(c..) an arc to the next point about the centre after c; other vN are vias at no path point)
+15: C1.1 C2.1 C19.1 J3.1 J6.3 pad.@76.85,54.1 pad.@99,61.6 pad.@101,61.945 U1.16 | length 80
  TOP w0.5: pad.@76.85,54.1 C2.1@77.5,54.75 78.625,54.75 C1.1@78.75,54.875 ; 82.75,74.5 83.75,75.5 ; 82.75,75.5 83.75,75.5 ; 82.75,76.5 83.75,75.5 ; pad.@99,61.6 99,73.25 96.75,75.5 83.75,75.5 ; pad.@101,61.945 J6.3@103,61.945
  TOP w0.6: C1.1@78.75,54.875 79.625,54.875 80.25,55.5
  TOP w1: 80.25,55.5 80.25,62.75 82.75,65.25 82.75,74.5 82.75,75.5 82.75,76.5 82.75,86.15 83,86.4 J3.1@83,91.25
  BOTTOM w0.5: U1.16@74.985,51.557 76.85,53.422 pad.@76.85,54.1 ; pad.@99,61.6 99.345,61.945 pad.@101,61.945
+15X: C40.1 J8.1 J9.3 pad.@115,61.25 pad.@137.25,33.75 pad.@138.25,33.75 | length 54.7
  TOP w0.5: J9.3@113,61.945 114.555,61.945 115,61.5 pad.@115,61.25 ; pad.@137.25,33.75 pad.@138.25,33.75 C40.1@139.5,33.75 140.75,33.75 141.5,33 J8.1@143.5,33
  BOTTOM w1: pad.@115,61.25 115,59 112.75,56.75 112.75,47.75 126.75,33.75 pad.@137.25,33.75 pad.@138.25,33.75
AD_UP_1: C30.1 R29.1 TP10.1 U2.32 U8.4 | length 32.6
  TOP w0.2: R29.1@93,63 C30.1@93,62 93,61.15 94.15,60 TP10.1@95.25,60 96.534,60 96.675,59.859 96.675,56.425 96,55.75 U8.4@94.05,55.75 ; U8.4@94.05,55.8 93,55.8 92.7,55.5 92.7,52.9 96.5,49.1 96.5,44.5 97,44 97,42 96.4,41.4 96.4,40 96.1,39.7 U2.32@95.35,39.7
AD_VDC_1: C37.1 D1.1 R4.2 R5.1 U2.35 | length 40.9
  TOP w0.2: D1.1@74.6,22.25 74.6,22.85 77.2,25.45 77.2,26.95 77.7,27.45 77.7,36.6 77.95,36.85 77.95,40.75 79.25,42.05 83.3,42.05 83.95,41.4 92.55,41.4 92.7,41.55 U2.35@92.7,42.35
  TOP w0.5: R4.2@70.35,22 70.6,21.75 R5.1@71.75,21.75 C37.1@72.75,21.75 74.1,21.75 D1.1@74.6,22.25
AD_VP_1: C33.1 R39.1 TP12.1 U2.33 U8.6 | length 32.4
  TOP w0.2: R39.1@90.5,63 C33.1@90.5,62 TP12.1@90.5,60 91.55,60 92.95,58.6 95.75,58.6 95.95,58.4 95.95,57.85 95.15,57.05 U8.6@94.05,57.05 92.8,57.05 92,56.25 92,53 96,49 96,44.25 96.5,43.75 96.5,42.25 95.35,41.1 U2.33@95.35,40.5
AD_WP_1: C34.1 R46.1 TP13.1 U2.34 U8.8 | length 29.8
  TOP w0.2: R46.1@87.25,63 C34.1@87.25,62 85.5,62 85,61.5 TP13.1@85,60 85,59 85.25,58.75 87.5,58.75 87.95,58.3 U8.8@87.95,57.7 89.1,57.7 90.1,56.7 90.1,54.3 95.55,48.85 95.55,45.95 93.6,44 93.6,42.45 U2.34@93.5,42.35
AGND: C6.2 C7.2 C11.1 C13.1 C30.2 C31.2 C32.2 C33.2 C34.2 C35.2 D4.1 D5.1 D6.1 pad.@81.5,62.25 pad.@81.25,59.75 pad.@81.75,54.5 pad.@83,56 pad.@83.75,64.5 pad.@84.225,70.725 pad.@85.25,55.25 pad.@86,67.25 pad.@88,71.75 pad.@88.25,63.5 pad.@89,68 pad.@89.25,55.75 pad.@89.25,62 pad.@90.75,49.25 pad.@90.75,50.25 pad.@90.75,51.25 pad.@91,55.5 pad.@91.5,63.5 pad.@91.5,68.25 pad.@91.75,49.25 pad.@91.75,50.25 pad.@91.75,51.25 pad.@92.25,62 pad.@93.35,70.5 pad.@94,63.5 pad.@94.65,53 pad.@95.5,63.25 pad.@96.75,66.25 R7.2 R8.1 R48.2 TP8.1 U2.38 U6.11 U8.10 U8.11 U8.12 | length 43.1
  TOP w0.2: R8.1@88.275,50.5 89.5,50.5
  TOP w0.3: pad.@86,67.25 U6.11@87.45,67.25 ; 88.95,56.4 U8.10@87.95,56.4 86.9,56.4 C35.2@86.5,56 C35.2@86.75,55.75 ; 89,55.1 U8.12@87.95,55.1 87.15,55.1 86.75,55.5 C35.2@86.75,55.75 ; pad.@89,55.75 U8.11@87.95,55.75 C35.2@86.75,55.75
  TOP w0.5: pad.@81.75,54.5 C32.2@81.75,55.375 82.95,55.375 ; pad.@84.225,70.725 84.25,70.7 84.25,71.65 D6.1@84.35,71.75 ; 84.25,56 R48.2@85.25,56 ; pad.@85.25,55.25 R48.2@85.25,56 ; C35.2@86.5,56 R48.2@85.25,56 ; pad.@88,71.75 D5.1@88.85,71.75 ; 88.25,61.45 C34.2@88.25,62 ; 88.25,62.8 C34.2@88.25,62 ; pad.@89.25,62 C34.2@88.25,62 ; U2.38@90.3,42.35 90.3,43.55 C6.2@90.5,43.75 90.5,44.875 C7.2@90.875,45.25 90.875,46.3 91.825,47.25 TP8.1@92.75,47.25 92.75,49.75 ; 91.5,61.45 C33.2@91.5,62 ; 91.5,62.85 C33.2@91.5,62 ; pad.@92.25,62 C33.2@91.5,62 ; pad.@93.35,70.5 D4.1@93.35,71.75 ; 94,61.45 C30.2@94,62 ; 94,63 C30.2@94,62 ; pad.@94.65,53 95.75,53 96.75,54 C31.2@96.75,55 ; 94.75,62 C30.2@94,62 ; 94.75,64.25 C13.1@95.25,64.25 ; pad.@95.25,63.25 C13.1@95.25,64.25 ; 96.25,63.25 R7.2@96.25,64.25 C13.1@95.25,64.25 ; pad.@96.75,66.25 C11.1@96.75,67.25 97.25,67.25
AVDD: C6.1 C7.1 C11.2 C31.1 C32.1 L1.1 pad.@83,58.25 pad.@87.75,48.75 pad.@95.75,54.25 pad.@95.75,66.25 pad.@97.25,63.25 R6.1 R33.1 TP9.1 U2.39 U6.4 U8.3 | length 71.9
  TOP w0.3: TP9.1@87.75,47.25 pad.@87.75,48.75 ; U6.4@93.55,67.25 C11.2@95.75,67.25 ; U8.3@94.05,55.1 95.1,55.1 95.2,55 C31.1@95.75,55
  TOP w0.5: R33.1@83,57 81.875,57 C32.1@81.75,57.125 81.75,58 82,58.25 pad.@83,58.25 ; L1.1@84.5,47.25 TP9.1@87.75,47.25 88.984,47.25 89.125,47.109 C7.1@89.125,45.25 89.125,44.125 C6.1@89.5,43.75 U2.39@89.5,42.35 ; pad.@95.75,54.25 C31.1@95.75,55 ; pad.@95.75,66.25 C11.2@95.75,67.25 ; pad.@97.25,63.25 R6.1@97.25,64.25
  BOTTOM w1: pad.@87.75,48.75 88.5,48 92.5,48 95.75,51.25 pad.@95.75,54.25 93.1,56.9 84.35,56.9 pad.@83,58.25 85.5,60.75 94.75,60.75 pad.@97.25,63.25 98.25,64.25 98.25,66.5 97.5,67.25 96.25,67.25 95.75,66.75 pad.@95.75,66.25
COMMD: J6.10 J7.6 pad.@88.25,44.75 pad.@105,50 pad.@105,57.5 R18.6 U2.40 | length 68.4
  TOP w0.2: pad.@88.25,44.75 88.25,44 88.7,43.55 U2.40@88.7,42.35 ; pad.@105,50 106.65,48.35 R18.6@106.65,46.8 ; pad.@105,57.5 105,58 105.135,58.135 J6.10@107,58.135 108.635,58.135 109.1,58.6 109.1,75.63 107.25,77.48 J7.6@105.77,77.48
  BOTTOM w0.2: pad.@88.25,44.75 88.65,45.15 94.95,45.15 98.8,49 98.8,56.6 99.7,57.5 pad.@105,57.5 105.75,57.5 106.8,56.45 106.8,52.65 105,50.85 pad.@105,50
DIAG: R43.1 U1.14 | length 10.4
  TOP w0.5: U1.14@74.985,48.001 76.1,48.001 76.601,47.5 79.25,47.5 79.6,47.85 79.6,52.275 R43.1@78.875,53
GND: C1.2 C2.2 C3.2 C4.2 C5.2 C14.2 C15.2 C16.2 C18.2 C19.2 C20.2 C21.2 C22.2 C24.2 C26.2 C27.2 J3.2 J6.20 J7.2 J10.2 pad.@77.5,51.25 pad.@77.8,26.25 pad.@77.75,45.75 pad.@77.75,46.75 pad.@78,57.75 pad.@78,58.75 pad.@78,59.75 pad.@78.75,45.75 pad.@78.75,46.75 pad.@78.75,51.25 pad.@79,57.75 pad.@79,58.75 pad.@79,59.75 pad.@80,85 pad.@80,90 pad.@80,95 pad.@80,100 pad.@81.5,34.25 pad.@82.75,46 pad.@83.75,30.75 pad.@85,85 pad.@85,95 pad.@85,100 pad.@86,32 pad.@86,36.5 pad.@86,40 pad.@86,45.5 pad.@90,40 pad.@90,85 pad.@90,90 pad.@90,100 pad.@91,32.25 pad.@91,36 pad.@93,38.5 pad.@94.2,32.25 pad.@94.2,35 pad.@94.5,30.5 pad.@95,95 pad.@95,100 pad.@96.5,34 pad.@96.6,35.45 pad.@96.15,31.45 pad.@97,77.5 pad.@97.1,48.75 pad.@97.5,31 pad.@97.75,43.35 pad.@98.25,60.25 pad.@99.25,39 pad.@99.75,26.75 pad.@100,90 pad.@100,95 pad.@100,100 pad.@100.75,69.25 pad.@100.125,36.05 pad.@102.25,34.75 pad.@103.5,44.25 pad.@104.75,44 pad.@105,65 pad.@105,85 pad.@105,90 pad.@105,95 pad.@105.75,44 pad.@106.75,44 pad.@107.1,50.7 pad.@107.65,69.25 pad.@107.75,44 pad.@108.25,21.75 pad.@108.25,78.9 pad.@108.25,88.5 pad.@108.65,29.95 R8.2 R9.1 R18.1 R18.2 R18.3 R18.4 R19.2 SW1.4 TP6.1 U1.1 U1.12 U1.18 U2.9 U2.25 U2.28 U5.3 Y1.2 Y1.4 | length 150.7
  TOP w0.2: 86.5,50.5 R8.2@87.925,50.5
  TOP w0.25: C26.2@97,78.5 96.5,79 96.5,80.55 96.7,80.75 U5.3@97.325,80.75
  TOP w0.3: C3.2@82.25,34.25 82.4,34.1 U2.9@83.65,34.1 ; U2.25@95.35,34.1 96.4,34.1 pad.@96.5,34 ; U2.28@95.35,36.5 96,36.5 96.65,37.15 96.65,37.3 98.25,38.9 C22.2@98.25,39 pad.@99.25,39 ; pad.@96.6,35.45 96.6,35.75 97.8,36.95 100.125,36.95 100.85,36.95 ; pad.@97.5,31 C16.2@98.25,31 98.25,32.2 Y1.4@97.85,32.6 ; C24.2@99.25,36.35 99.25,35.3 Y1.2@99.65,34.9 101.2,34.9 ; pad.@104.75,44 105.05,44.3 R18.1@105.05,45.2 ; pad.@105.75,44 105.85,44.1 R18.2@105.85,45.2 ; R18.3@106.65,45.2 106.65,44.1 pad.@106.75,44 ; R18.4@107.45,45.2 107.45,44.3 pad.@107.75,44
  TOP w0.4: U2.9@83.65,34.1 84.55,34.1
  TOP w0.5: U1.12@74.985,44.445 76.445,44.445 pad.@77.75,45.75 ; 74.985,56.5 U1.18@74.985,55.113 76.35,55.113 ; 76.65,55.75 C2.2@77.5,55.75 77.5,56.8 ; 77,50.25 C15.2@77.5,50.25 pad.@77.5,51.25 ; 77.85,56.625 C1.2@78.75,56.625 pad.@78.75,57.65 ; C14.2@78.75,50.375 pad.@78.75,51.25 ; 79.85,97.5 J3.2@83,97.5 ; 80,89 C19.2@81.375,89 ; 81.375,88.05 C19.2@81.375,89 ; 81.375,89.9 C19.2@81.375,89 ; pad.@81.5,34.25 C3.2@82.25,34.25 ; 83,95.15 J3.2@83,97.5 ; 83,99.25 J3.2@83,97.5 ; 85.3,79.925 SW1.4@85.925,79.925 ; 85.925,78.75 SW1.4@85.925,79.925 ; 85.925,81.2 SW1.4@85.925,79.925 ; 86.2,97.5 J3.2@83,97.5 ; 86.6,79.925 SW1.4@85.925,79.925 ; 92,97.5 J10.2@95,97.5 ; 93.25,77.875 C27.2@94,77.875 ; 94,77.05 C27.2@94,77.875 ; 94.95,77.875 C27.2@94,77.875 ; 95,95.4 J10.2@95,97.5 ; 95,99.45 J10.2@95,97.5 ; 96.875,88.25 C18.2@96.875,89.25 ; 96.875,90.1 C18.2@96.875,89.25 ; pad.@97,77.5 C26.2@97,78.5 97.8,78.5 ; 97.8,28.25 C4.2@98.75,28.25 98.75,27.3 ; 97.9,89.25 C18.2@96.875,89.25 ; 98.55,97.5 J10.2@95,97.5 ; 100,27 C5.2@100,27.875 100.8,27.875 ; pad.@100.125,36.05 100.125,36.95 C20.2@100.125,37.75 ; 100.125,38.75 C20.2@100.125,37.75 ; 100.125,40.5 C21.2@100.125,41.25 ; 101.25,37.75 C20.2@100.125,37.75 ; 102.45,92.25 TP6.1@105.25,92.25 ; pad.@103.5,44.25 R19.2@103.5,45.125 ; pad.@105.25,90.15 TP6.1@105.25,92.25 ; 105.25,94.6 TP6.1@105.25,92.25 ; 105.77,84.7 J7.2@105.77,82.56 107.7,82.56 ; J6.20@107,51.785 108.75,51.785 ; 108.3,92.25 TP6.1@105.25,92.25
  BOTTOM w0.2: 108.25,67.35 108.9,66.7 108.9,47.15 108.75,47
  BOTTOM w0.5: 74.985,23.3 U1.1@74.985,24.887 76.15,24.887 ; U1.12@74.985,44.445 77.3,44.445 ; U1.18@74.985,55.113 76.3,55.113 ; 80.5,97.5 J3.2@83,97.5 ; 83,95.75 J3.2@83,97.5 ; 83,99.25 J3.2@83,97.5 ; 86,97.5 J3.2@83,97.5 ; 92.5,97.5 J10.2@95,97.5 ; 95,96 J10.2@95,97.5 ; 95,99.25 J10.2@95,97.5 ; 98,97.5 J10.2@95,97.5 ; 105.77,84.45 J7.2@105.77,82.56 107.35,82.56
GNDX: C25.2 C29.2 C38.2 C39.2 C40.2 J4.2 J4.2-2 J5.3 J5.5 J5.9 J5.15 J5.17 J5.19 J8.3 J8.5 J9.20 JP1.2 LEDP2.2 pad.@113.25,89.5 pad.@115,30 pad.@115,35 pad.@115,40 pad.@115,50 pad.@115,80 pad.@115,90 pad.@115,95 pad.@115.25,81.25 pad.@117.65,87.7 pad.@119,65.75 pad.@120,25 pad.@120,30 pad.@120,35 pad.@120,45 pad.@120,50 pad.@120,77 pad.@120,95 pad.@120,100 pad.@121.9,81.85 pad.@123.15,87.75 pad.@125,25 pad.@125,30 pad.@125,40 pad.@125,45 pad.@125,50 pad.@125,55 pad.@125,65.75 pad.@125,77 pad.@126.95,87.65 pad.@127.1,82.35 pad.@130,30 pad.@130,35 pad.@130,40 pad.@130,45 pad.@130,50 pad.@130,55 pad.@130,65 pad.@130,77 pad.@131,65.75 pad.@132.3,82.2 pad.@133,91.25 pad.@133,92.5 pad.@133.1,87.6 pad.@134,79.25 pad.@135,25 pad.@135,30 pad.@135,35 pad.@135,50 pad.@135,65 pad.@135,80 pad.@135,85 pad.@137,65.75 pad.@138.25,34.75 pad.@138.25,37.25 pad.@139.3,82.55 pad.@140,25 pad.@140,30 pad.@140,40 pad.@140,45 pad.@140,50 pad.@140,60 pad.@140,65 pad.@140,90 pad.@140,95 pad.@140,100 pad.@141,69.035 pad.@141,70.25 pad.@141,71.5 pad.@141,75.25 pad.@141,77.75 pad.@141,79 pad.@145,35 pad.@145,40 pad.@145,45 pad.@145,50 pad.@145,55 pad.@145,60 pad.@145,85 pad.@145,90 pad.@145,95 R25.2 R30.2 R36.2 R50.2 R51.2 R52.2 R53.2 S_SW1.3 S_SW2.3 S_SW3.3 S_SW4.3 U7.4 VR1.1 | length 125.5
  TOP w0.25: 114.75,82 U7.4@114.75,83 114.75,84
  TOP w0.5: 112.55,88.5 C29.2@113.25,88.5 pad.@113.25,89.2 ; 116.7,69.5 S_SW1.3@117.85,69.5 ; 117,51.01 J9.20@117,51.785 118.85,51.785 ; 117.85,68.35 S_SW1.3@117.85,69.5 ; 117.85,70.65 S_SW1.3@117.85,69.5 ; 118.3,66.75 R50.2@119,66.75 ; pad.@119,66.05 R50.2@119,66.75 ; 119,67.45 R50.2@119,66.75 ; 119,69.5 S_SW1.3@117.85,69.5 ; 119.3,78 R25.2@120,78 ; pad.@120,77.3 R25.2@120,78 ; 120.7,78 R25.2@120,78 ; 122.7,69.5 S_SW2.3@123.85,69.5 ; 123.85,68.35 S_SW2.3@123.85,69.5 ; 123.85,70.65 S_SW2.3@123.85,69.5 ; 124.3,66.75 R51.2@125,66.75 ; 124.3,78 R30.2@125,78 ; 124.875,26 VR1.1@126.375,26 ; pad.@125,66.05 R51.2@125,66.75 ; 125,67.45 R51.2@125,66.75 ; 125,69.5 S_SW2.3@123.85,69.5 ; pad.@125,77.3 R30.2@125,78 ; 125.7,78 R30.2@125,78 ; 126.375,24.5 VR1.1@126.375,26 ; 126.375,27.5 VR1.1@126.375,26 ; 127.05,23.25 C38.2@127.75,23.25 127.75,23.95 ; 127.875,26 VR1.1@126.375,26 ; 128.7,69.5 S_SW3.3@129.85,69.5 ; 129.3,78 R36.2@130,78 ; 129.85,68.35 S_SW3.3@129.85,69.5 ; 129.85,70.65 S_SW3.3@129.85,69.5 ; pad.@130,77.3 R36.2@130,78 ; 130.3,66.75 R52.2@131,66.75 ; 130.7,78 R36.2@130,78 ; pad.@131,66.05 R52.2@131,66.75 ; 131,67.45 R52.2@131,66.75 ; 131,69.5 S_SW3.3@129.85,69.5 ; 132.25,93.5 C25.2@133.125,93.5 ; 132.86,95.6 J4.2-2@132.86,97.21 132.86,98.9 ; 132.86,100.25 J4.2@132.86,102.29 132.86,103.75 ; pad.@133.125,92.5 C25.2@133.125,93.5 ; 133.125,94.5 C25.2@133.125,93.5 ; 133.15,80.75 LEDP2.2@134,80.75 ; 134,79.9 LEDP2.2@134,80.75 ; 134.7,69.5 S_SW4.3@135.85,69.5 ; 134.85,80.75 LEDP2.2@134,80.75 ; 135.85,68.35 S_SW4.3@135.85,69.5 ; 135.85,70.65 S_SW4.3@135.85,69.5 ; 136.3,66.75 R53.2@137,66.75 ; pad.@137,66.05 R53.2@137,66.75 ; 137,67.45 R53.2@137,66.75 ; 137,69.5 S_SW4.3@135.85,69.5 ; pad.@138.25,34.75 C40.2@139.5,34.75 ; pad.@138.25,37.25 C39.2@139.5,37.25 ; 139.5,35.45 C40.2@139.5,34.75 ; 139.5,37.95 C39.2@139.5,37.25 ; 140.2,34.75 C40.2@139.5,34.75 ; 140.5,37.25 C39.2@139.5,37.25 ; pad.@141.15,69.035 J5.19@143,69.035 ; pad.@141.15,70.305 J5.17@143,70.305 ; pad.@141.15,71.575 J5.15@143,71.575 ; pad.@141.15,75.385 J5.9@143,75.385 ; pad.@141.15,77.925 J5.5@143,77.925 ; pad.@141.15,79.195 J5.3@143,79.195 ; 142.25,38 J8.3@143.5,38 144.75,38 ; 142.25,43 J8.5@143.5,43 ; 143.5,44.25 J8.5@143.5,43 ; 144.27,51.95 JP1.2@144.27,53.25 ; 144.27,54.55 JP1.2@144.27,53.25 ; 144.75,43 J8.5@143.5,43 ; 145.57,53.25 JP1.2@144.27,53.25
  BOTTOM w0.5: 117.85,68.35 S_SW1.3@117.85,69.5 ; 117.85,70.65 S_SW1.3@117.85,69.5 ; 119,69.5 S_SW1.3@117.85,69.5 ; 122.7,69.5 S_SW2.3@123.85,69.5 ; 123.85,68.35 S_SW2.3@123.85,69.5 ; 123.85,70.65 S_SW2.3@123.85,69.5 ; 124.875,26 VR1.1@126.375,26 ; 125,69.5 S_SW2.3@123.85,69.5 ; 126.375,24.5 VR1.1@126.375,26 ; 126.375,27.5 VR1.1@126.375,26 ; 127.875,26 VR1.1@126.375,26 ; 128.7,69.5 S_SW3.3@129.85,69.5 ; 129.85,68.35 S_SW3.3@129.85,69.5 ; 129.85,70.65 S_SW3.3@129.85,69.5 ; 131,69.5 S_SW3.3@129.85,69.5 ; 132.86,95.5 J4.2-2@132.86,97.21 132.86,99 ; 132.86,100.5 J4.2@132.86,102.29 132.86,103.5 ; 134.7,69.5 S_SW4.3@135.85,69.5 ; 135.85,68.35 S_SW4.3@135.85,69.5 ; 135.85,70.65 S_SW4.3@135.85,69.5 ; 137,69.5 S_SW4.3@135.85,69.5 ; 142.25,38 J8.3@143.5,38 144.75,38 ; 142.25,43 J8.5@143.5,43 ; 143.5,44.25 J8.5@143.5,43 ; 144.27,51.95 JP1.2@144.27,53.25 ; 144.27,54.55 JP1.2@144.27,53.25 ; 144.75,43 J8.5@143.5,43 ; 145.57,53.25 JP1.2@144.27,53.25
GPIO_MAIN: J7.8 pad.@90.4,29.5 U2.18 | length 59.8
  TOP w0.2: U2.18@90.3,30.65 90.4,30.55 pad.@90.4,29.5
  BOTTOM w0.2: pad.@90.4,29.5 89.95,29.95 89.95,36.35 93.1,39.5 96.15,39.5 101.85,45.2 105.95,45.2 108.5,47.75 108.5,66 105.77,68.73 J7.8@105.77,74.94
KEY_1: J6.9 J7.5 pad.@87.25,44.75 pad.@101,58.135 pad.@105.75,50.75 R18.5 U2.41 | length 75.3
  TOP w0.2: pad.@87.25,44.75 87.25,44 87.9,43.35 U2.41@87.9,42.35 ; pad.@101,58.135 J6.9@103,58.135 104.535,58.135 105.17,58.77 108.559,58.77 108.7,58.911 108.7,75.25 107.74,76.21 104.5,76.21 J7.5@103.23,77.48 ; pad.@105.75,50.75 107.45,49.05 R18.5@107.45,46.8
  BOTTOM w0.2: pad.@87.25,44.75 88.05,45.55 94.75,45.55 98.4,49.2 98.4,56.9 99.635,58.135 pad.@101,58.135 105.965,58.135 107.2,56.9 107.2,52.2 pad.@105.75,50.75
KEY_3: J6.11 pad.@91.5,44 pad.@101,56.865 pad.@104.25,49.25 R18.7 U2.37 | length 39.6
  TOP w0.2: U2.37@91.1,42.35 91.1,43.6 pad.@91.5,44 ; pad.@101,56.865 J6.11@103,56.865 ; pad.@104.25,49.25 105.85,47.65 R18.7@105.85,46.8
  BOTTOM w0.2: pad.@91.5,44 92.25,44.75 95.15,44.75 99.2,48.8 99.2,56.2 99.865,56.865 pad.@101,56.865 105.685,56.865 106.4,56.15 106.4,52.95 104.25,50.8 pad.@104.25,49.25
KEY_4: J6.12 pad.@84.75,29.75 pad.@103.5,48.5 pad.@105,56.25 R18.8 U2.12 | length 63.7
  TOP w0.2: pad.@84.75,29.75 85.359,29.75 85.5,29.891 U2.12@85.5,30.65 ; pad.@103.5,48.5 105.05,46.95 R18.8@105.05,46.8 ; pad.@105,56.25 105,56.75 105.115,56.865 J6.12@107,56.865
  BOTTOM w0.2: pad.@84.75,29.75 86.6,31.6 86.6,40.65 83.75,43.5 83.75,44 84.25,44.5 86.6,44.5 87.7,43.4 91.9,43.4 92.25,43.75 92.25,44 92.6,44.35 95.35,44.35 99.6,48.6 99.6,55.85 100,56.25 pad.@105,56.25 105.45,56.25 106,55.7 106,53.25 103.5,50.75 pad.@103.5,48.5
KEY_A: J6.13 pad.@93,43.75 pad.@101,55.595 pad.@102.75,47.75 R19.1 U2.36 | length 35.7
  TOP w0.2: U2.36@91.9,42.35 91.9,43.3 92.35,43.75 pad.@93,43.75 ; pad.@101,55.595 J6.13@103,55.595 ; pad.@102.75,47.75 102.975,47.4 R19.1@103.5,46.875
  BOTTOM w0.2: pad.@93,43.75 95.35,43.75 100,48.4 100,55.15 100.445,55.595 pad.@101,55.595 101.416,55.65 105.245,55.65 105.6,55.295 105.6,53.45 102.75,50.6 pad.@102.75,47.75
KEYX_1: J9.9 pad.@120,65.75 pad.@127.5,60 R50.1 S_SW1.2 | length 32.8
  TOP w0.2: J9.9@113,58.135 114.615,58.135 115.25,57.5 121.05,57.5 123.55,60 pad.@127.5,60 ; S_SW1.2@117.85,72 119.75,70.1 119.75,67 R50.1@120,66.75 pad.@120,65.75
  BOTTOM w0.2: pad.@120,65.75 121.75,65.75 pad.@127.5,60
KEYX_2: J9.10 pad.@126,65.75 pad.@129,60 R51.1 S_SW2.2 | length 27.5
  TOP w0.2: J9.10@117,58.135 120.885,58.135 123.5,60.75 128.25,60.75 pad.@129,60 ; S_SW2.2@123.85,72 125.75,70.1 125.75,67 R51.1@126,66.75 pad.@126,65.75
  BOTTOM w0.2: pad.@126,65.75 126,64.75 129,61.75 pad.@129,60
KEYX_3: J9.11 pad.@132,60.5 pad.@132,65.75 R52.1 S_SW3.2 | length 33.4
  TOP w0.2: J9.11@113,56.865 114.635,56.865 115.27,56.23 121.48,56.23 124.25,59 130.5,59 pad.@132,60.5 ; S_SW3.2@129.85,72 131.75,70.1 131.75,67 R52.1@132,66.75 pad.@132,65.75
  BOTTOM w0.2: pad.@132,60.5 pad.@132,65.75
KEYX_4: J9.12 pad.@130.25,59.75 pad.@138,65.75 R53.1 S_SW4.2 | length 33.5
  TOP w0.2: J9.12@117,56.865 121.215,56.865 123.75,59.4 129.9,59.4 pad.@130.25,59.75 ; S_SW4.2@135.85,72 137.75,70.1 137.75,67 R53.1@138,66.75 pad.@138,65.75
  BOTTOM w0.2: pad.@130.25,59.75 131,59.75 131.75,59 133,59 138,64 pad.@138,65.75
KEYX_A: C38.1 J9.13 VR1.2 | length 50.5
  TOP w0.2: J9.13@113,55.595 114.155,55.595 114.79,54.96 120.79,54.96 121.75,54 121.75,25 124.75,22 127.5,22 C38.1@128.75,23.25 130.125,24.625 VR1.2@130.125,26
